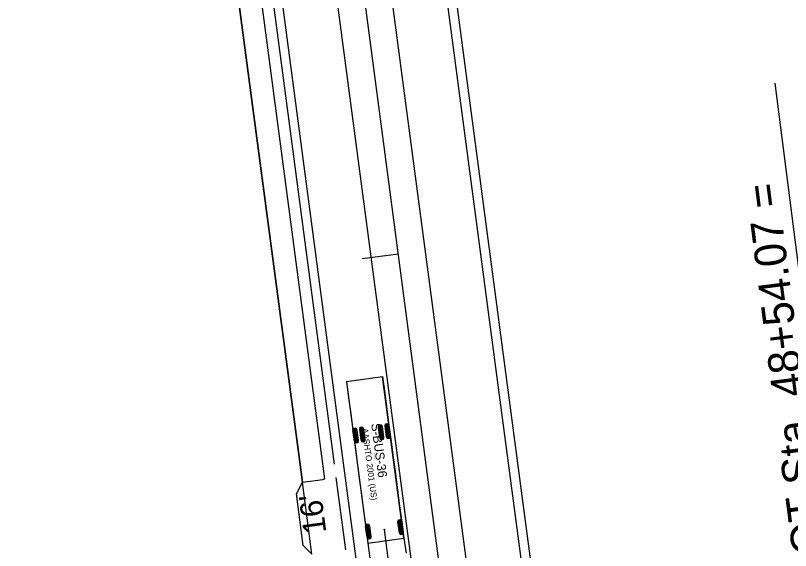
# Model space of a CAD drawing. Extents: x 2367848 to 2369479, y 800728 to 808616.
# Drawn here: x 2368641.4 to 2368811.9, y 805258 to 805375.7 of the extents above; entities that cross this region are included whole.
import ezdxf

# ---------------------------------------------------------------- set-up
doc = ezdxf.new("R2010")
doc.units = 0
for name, color, linetype in [('Prop AutoTurn Projected Path', 7, 'Continuous'), ('Prop AutoTurn Simulation', 7, 'Continuous'), ('Prop Conc 2ft 6in Curb and Gutter', 7, 'Continuous'), ('Prop Conc 4in Sidewalk', 7, 'Continuous'), ('Prop Conc Drive Radius Type', 7, 'Continuous'), ('Prop Conc Driveway', 7, 'Continuous'), ('Prop Dimension', 7, 'Continuous'), ('Prop EOT', 7, 'Continuous'), ('Prop Horizontal Alignment', 7, 'Continuous'), ('Prop Horizontal Alignment Station Label', 7, 'Continuous'), ('Prop Horizontal Alignment Tick Large', 7, 'Continuous'), ('Prop Lane Lines', 7, 'Continuous'), ('Prop Shade Light', 7, 'Continuous')]:
    doc.layers.add(name, color=color, linetype=linetype)

msp = doc.modelspace()

# ---------------------------------------------------------------- linework, layer by layer
at = {"layer": 'Prop AutoTurn Projected Path'}
msp.add_line((2368727.34, 805226.46), (2368722.54, 805262.68), dxfattribs=at)
at = {"layer": 'Prop AutoTurn Simulation'}
for p, q in [((2368722.14, 805296.21), (2368714.21, 805295.16)), ((2368726.84, 805260.72), (2368722.14, 805296.21)), ((2368714.21, 805295.16), (2368718.91, 805259.67)), ((2368721.82, 805282.38), (2368721.39, 805285.69)), ((2368722.03, 805282.41), (2368721.59, 805285.72)), ((2368722.24, 805282.44), (2368721.8, 805285.74)), ((2368723.31, 805282.58), (2368722.87, 805285.89)), ((2368723.52, 805282.61), (2368723.08, 805285.91)), ((2368723.72, 805282.64), (2368723.29, 805285.94)), ((2368716.21, 805281.64), (2368715.77, 805284.95)), ((2368716.41, 805281.67), (2368715.98, 805284.97)), ((2368716.62, 805281.7), (2368716.18, 805285)), ((2368717.69, 805281.84), (2368717.26, 805285.14)), ((2368717.9, 805281.87), (2368717.46, 805285.17)), ((2368718.11, 805281.89), (2368717.67, 805285.2)), ((2368726.31, 805261.49), (2368725.88, 805264.8)), ((2368726.52, 805261.52), (2368726.08, 805264.83)), ((2368719, 805260.53), (2368718.57, 805263.83)), ((2368719.21, 805260.55), (2368718.77, 805263.86)), ((2368719.42, 805260.58), (2368718.98, 805263.88)), ((2368726.11, 805261.47), (2368725.67, 805264.77)), ((2368718.91, 805259.67), (2368726.84, 805260.72)), ((2368726.84, 805260.72), (2368726.84, 805260.72))]:
    msp.add_line(p, q, dxfattribs=at)
for points in [[(2368722.14, 805296.21), (2368722.61, 805292.66), (2368723.08, 805289.11), (2368723.55, 805285.56), (2368724.02, 805282.02), (2368724.49, 805278.47), (2368724.96, 805274.92), (2368725.43, 805271.37), (2368725.9, 805267.82), (2368726.37, 805264.27), (2368726.84, 805260.72), (2368726.84, 805260.72), (2368727.32, 805257.41)], [(2368714.21, 805295.16), (2368714.68, 805291.61), (2368715.15, 805288.06), (2368715.62, 805284.51), (2368716.09, 805280.97), (2368716.56, 805277.42), (2368717.03, 805273.87), (2368717.5, 805270.32), (2368717.97, 805266.77), (2368718.44, 805263.22), (2368718.91, 805259.67), (2368718.91, 805259.67), (2368718.91, 805259.67), (2368719.35, 805256.35)]]:
    msp.add_lwpolyline(points, dxfattribs=at)
for points in [[(2368722.29, 805282.45), (2368721.77, 805282.38), (2368721.56, 805282.82), (2368721.24, 805285.2), (2368721.34, 805285.68), (2368721.85, 805285.75), (2368722.07, 805285.31), (2368722.38, 805282.93)], [(2368723.78, 805282.64), (2368723.26, 805282.57), (2368723.04, 805283.02), (2368722.73, 805285.4), (2368722.82, 805285.88), (2368723.34, 805285.95), (2368723.55, 805285.51), (2368723.87, 805283.13)], [(2368716.67, 805281.7), (2368716.16, 805281.63), (2368715.94, 805282.08), (2368715.62, 805284.46), (2368715.72, 805284.94), (2368716.23, 805285.01), (2368716.45, 805284.56), (2368716.77, 805282.19)], [(2368718.16, 805281.9), (2368717.64, 805281.83), (2368717.43, 805282.27), (2368717.11, 805284.65), (2368717.21, 805285.14), (2368717.72, 805285.2), (2368717.94, 805284.76), (2368718.25, 805282.38)], [(2368726.57, 805261.53), (2368726.06, 805261.46), (2368725.84, 805261.9), (2368725.52, 805264.28), (2368725.62, 805264.76), (2368726.13, 805264.83), (2368726.35, 805264.39), (2368726.67, 805262.01)], [(2368719.47, 805260.59), (2368718.95, 805260.52), (2368718.73, 805260.96), (2368718.42, 805263.34), (2368718.51, 805263.82), (2368719.03, 805263.89), (2368719.25, 805263.45), (2368719.56, 805261.07)]]:
    msp.add_lwpolyline(points, close=True, dxfattribs=at)
for centre in [(2368722.14, 805296.21), (2368714.21, 805295.16), (2368722.54, 805262.68)]:
    msp.add_circle(centre, 0.0417, dxfattribs=at)
at = {"layer": 'Prop Conc 2ft 6in Curb and Gutter'}
for p, q in [((2368758.08, 805230.44), (2368673.39, 805870.04)), ((2368711.56, 805277.05), (2368675.7, 805547.86))]:
    msp.add_line(p, q, dxfattribs=at)
at = {"layer": 'Prop Conc 4in Sidewalk'}
for p, q in [((2368704.52, 805273.09), (2368668.27, 805546.88)), ((2368709.47, 805273.79), (2368673.23, 805547.53))]:
    msp.add_line(p, q, dxfattribs=at)
msp.add_arc((2368708.58, 805276.66), 3, 277.5806, 287.1687, dxfattribs=at)
at = {"layer": 'Prop Conc Drive Radius Type'}
msp.add_line((2368714.05, 805258.21), (2368711.95, 805274.08), dxfattribs=at)
at = {"layer": 'Prop Conc Driveway'}
for p, q in [((2368704.52, 805273.09), (2368708.98, 805273.68)), ((2368706.62, 805257.23), (2368704.52, 805273.09))]:
    msp.add_line(p, q, dxfattribs=at)
at = {"layer": 'Prop EOT'}
for p, q in [((2368756.1, 805230.18), (2368665.18, 805916.87)), ((2368717.02, 805251.03), (2368677.69, 805548.12)), ((2368703.18, 805270.51), (2368704.52, 805273.09)), ((2368704.7, 805259.14), (2368703.18, 805270.51)), ((2368706.62, 805257.23), (2368704.7, 805259.14))]:
    msp.add_line(p, q, dxfattribs=at)
at = {"layer": 'Prop Horizontal Alignment'}
msp.add_line((2368753.14, 805115.37), (2368647.33, 805914.51), dxfattribs=at)
at = {"layer": 'Prop Horizontal Alignment Station Label'}
msp.add_line((2368824.19, 805238), (2368808.5, 805360.84), dxfattribs=at)
at = {"layer": 'Prop Horizontal Alignment Tick Large'}
msp.add_line((2368725.62, 805323.21), (2368717.69, 805322.16), dxfattribs=at)
msp.add_line((2368725.62, 805323.21), (2368717.69, 805322.16), dxfattribs=at)
at = {"layer": 'Prop Lane Lines'}
for p, q in [((2368759.09, 805116.16), (2368653.28, 805915.29)), ((2368747.19, 805114.58), (2368641.38, 805913.72))]:
    msp.add_line(p, q, dxfattribs=at)
at = {"layer": 'Prop Shade Light'}
for p, q in [((2368668.27, 805546.88), (2368704.52, 805273.09)), ((2368709.47, 805273.79), (2368673.23, 805547.53)), ((2368704.52, 805273.09), (2368708.98, 805273.68))]:
    msp.add_line(p, q, dxfattribs=at)
msp.add_arc((2368708.58, 805276.66), 3, 277.5806, 287.1687, dxfattribs=at)

# ---------------------------------------------------------------- texts
at = {"layer": 'Prop AutoTurn Simulation'}
for s, height, p in [('S-BUS-36', 2, (2368719.63, 805285.89)), ('AASHTO 2001 (US)', 1.3333, (2368717.59, 805284.83)), ('(c) 2014 Transoft Solutions, Inc. All rights reserved.', 0.08, (2368720.27, 805279.55))]:
    msp.add_text(s, height=height, rotation=277.5424, dxfattribs=at).set_placement(p)
at = {"layer": 'Prop Dimension'}
msp.add_text("16'", height=5, rotation=97.5424, dxfattribs=at).set_placement((2368709.79, 805262.02))
at = {"layer": 'Prop Horizontal Alignment Station Label'}
msp.add_text('-L- POT Sta. 48+54.07 =', height=7, rotation=97.2784, dxfattribs=at).set_placement((2368821.94, 805237.53))

doc.saveas('drawing.dxf')
